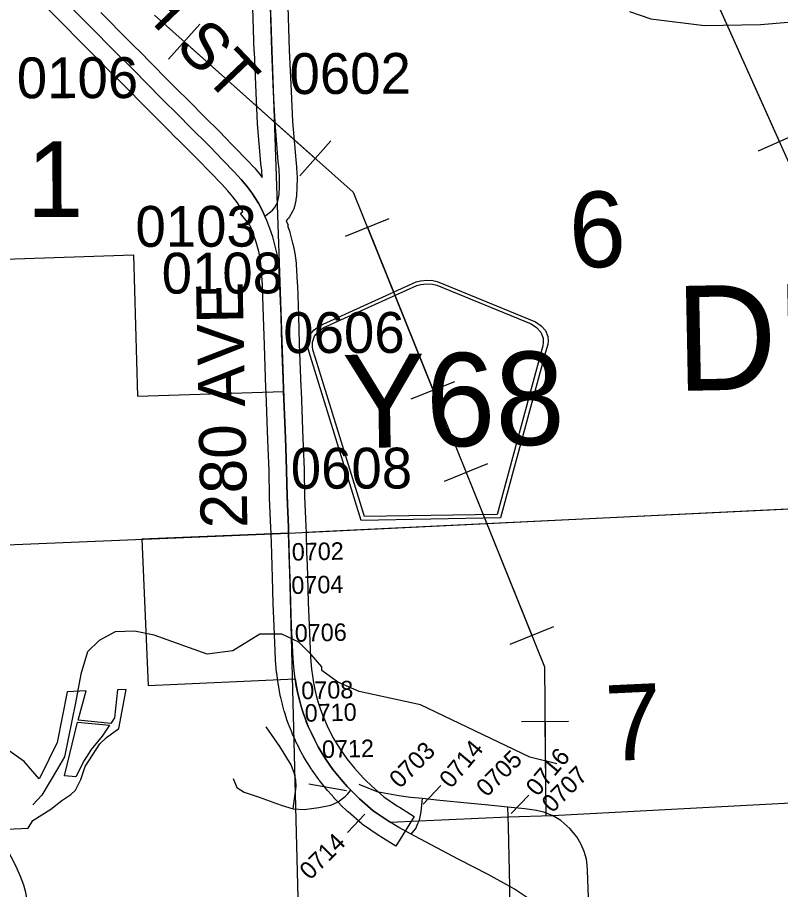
# Model space of a CAD drawing. Extents: x 128.7 to 185.5, y -21.4 to 12.6.
# Drawn here: x 151.757 to 153.067, y -8.747 to -7.251 of the extents above; entities that cross this region are included whole.
import ezdxf

# ---------------------------------------------------------------- set-up
doc = ezdxf.new("R2010")
doc.units = 0
for name, color, linetype in [('tdCoCityStreetMajor', 7, 'Continuous'), ('tdCoCityStreetMinor', 7, 'Continuous'), ('tdCoCorpBndry', 7, 'Continuous'), ('tdCoHydroRiver', 7, 'Continuous'), ('tdCoPipe', 7, 'Continuous'), ('tdCoSecRdNmbr', 7, 'Continuous'), ('tdCoSecRdTxt', 7, 'Continuous'), ('tdCoSecRteBand', 7, 'Continuous'), ('tdCoSecRteCL', 7, 'Continuous'), ('tdCoSectLine', 7, 'Continuous'), ('tdCoSectLinePart', 7, 'Continuous'), ('tdCoSectNmbr', 7, 'Continuous'), ('tdCoShieldCoRte', 7, 'Continuous'), ('tdCoSurfAsphalt', 7, 'Continuous'), ('tdCoSurfAsphaltUnbanded', 7, 'Continuous'), ('tdCoSurfBitumUnbanded', 7, 'Continuous'), ('tdCoSurfConc', 7, 'Continuous'), ('tdCoSurfConcUnbanded', 7, 'Continuous'), ('tdCoSurfGravel', 7, 'Continuous'), ('tdCoTwpNameTxt', 7, 'Continuous')]:
    doc.layers.add(name, color=color, linetype=linetype)

msp = doc.modelspace()

# ---------------------------------------------------------------- linework, layer by layer
at = {"layer": 'tdCoCityStreetMajor'}
for points in [[(152.4331, -8.6525), (152.4116, -8.6408), (152.3969, -8.6317)], [(152.4331, -8.6525), (152.4407, -8.6425), (152.4446, -8.6344), (152.4465, -8.6295)], [(152.6973, -8.8273), (152.7376, -8.7985), (152.7378, -8.7758), (152.7356, -8.7146), (152.7348, -8.7057), (152.7339, -8.6956), (152.7297, -8.6821), (152.724, -8.6692), (152.7174, -8.6572), (152.705, -8.6426), (152.6895, -8.629), (152.6754, -8.6202)], [(151.7671, -8.9262), (151.768, -8.9191), (151.7702, -8.9109), (151.7737, -8.8995), (151.7772, -8.8867), (151.7796, -8.8783), (151.779, -8.8627), (151.7774, -8.8133), (151.7764, -8.7894), (151.7758, -8.776), (151.7742, -8.7652), (151.7715, -8.7525), (151.7682, -8.7402), (151.7623, -8.7253), (151.7569, -8.712), (151.7489, -8.6955), (151.7465, -8.6911), (151.7403, -8.6792), (151.7302, -8.6651), (151.7132, -8.6461), (151.7123, -8.6452)], [(152.6973, -8.8273), (152.6944, -8.8228), (152.6742, -8.7979), (152.6584, -8.7828), (152.6409, -8.7673), (152.6103, -8.7466), (152.6022, -8.7421), (152.5652, -8.7219), (152.5146, -8.6958), (152.4392, -8.6558), (152.4331, -8.6525)]]:
    msp.add_lwpolyline(points, dxfattribs=at)
at = {"layer": 'tdCoCityStreetMinor'}
for points in [[(152.2306, -8.6088), (152.2356, -8.5706), (152.2353, -8.5597), (152.2326, -8.5491), (152.2269, -8.5333), (152.2075, -8.5018), (152.1843, -8.4682)], [(152.1274, -8.5567), (152.1337, -8.5724), (152.1466, -8.5802), (152.1724, -8.5888), (152.2099, -8.6026), (152.2306, -8.6088)], [(152.2306, -8.6088), (152.2496, -8.6103), (152.2745, -8.6068), (152.2953, -8.6024), (152.3075, -8.5972), (152.3199, -8.5876), (152.3243, -8.5831), (152.3296, -8.5772)], [(152.6034, -8.8485), (152.6029, -8.8327), (152.6025, -8.7563), (152.6022, -8.7421), (152.6002, -8.6399), (152.5996, -8.6227)]]:
    msp.add_lwpolyline(points, dxfattribs=at)
at = {"layer": 'tdCoCorpBndry'}
for points in [[(151.7011, -7.6673), (151.9564, -7.6586), (151.9636, -7.9008), (152.214, -7.8933), (152.2167, -7.9596), (152.2177, -7.9885), (152.2192, -8.0277), (152.2199, -8.0738), (152.2224, -8.1256), (152.2227, -8.1359), (151.9705, -8.1465), (151.9819, -8.3974), (152.2338, -8.3859), (152.236, -8.3993), (152.2384, -8.4109), (152.2411, -8.4222), (152.2442, -8.4333), (152.2455, -8.4374), (152.2476, -8.4444), (152.2515, -8.4553), (152.2564, -8.4675), (152.2617, -8.4794), (152.2674, -8.4912), (152.2736, -8.5027), (152.2802, -8.5141), (152.2872, -8.5251), (152.2988, -8.5414), (152.3129, -8.5586), (152.3232, -8.5705), (152.3296, -8.5772), (152.3326, -8.5803), (152.3445, -8.5917), (152.3679, -8.6122), (152.3933, -8.6294), (152.3969, -8.6317), (152.4465, -8.6295), (152.5996, -8.6227), (152.6754, -8.6202), (153.2238, -8.591)], [(151.7153, -8.645), (151.776, -8.642), (151.7836, -8.6288), (151.8147, -8.6093), (151.8334, -8.5948), (151.8487, -8.5842), (151.8571, -8.5767), (151.8659, -8.5587), (151.8738, -8.5362), (151.899, -8.4974), (151.91, -8.4868), (151.9316, -8.4714), (151.9439, -8.404), (151.9293, -8.4046), (151.9239, -8.4528), (151.9174, -8.4623), (151.8617, -8.4569), (151.875, -8.4067), (151.8429, -8.4082), (151.8256, -8.4949), (151.7967, -8.5536), (151.7947, -8.5576), (151.7688, -8.5277), (151.7376, -8.5053)]]:
    msp.add_lwpolyline(points, dxfattribs=at)
msp.add_lwpolyline([(151.8576, -8.5541), (151.838, -8.5524), (151.8605, -8.4602), (151.9152, -8.4655), (151.9025, -8.4841), (151.8841, -8.5072), (151.8718, -8.5259)], close=True, dxfattribs=at)
at = {"layer": 'tdCoHydroRiver'}
for points in [[(152.8074, -7.2411), (152.8441, -7.254), (152.9361, -7.2651), (153.0323, -7.2634), (153.1613, -7.2526)], [(152.6828, -8.5317), (152.6366, -8.5206), (152.4489, -8.4308), (152.3439, -8.4076), (152.3071, -8.3915), (152.2796, -8.3719), (152.2794, -8.3656), (152.2613, -8.3441), (152.24, -8.3228), (152.2111, -8.3095), (152.1733, -8.3093), (152.1269, -8.3377), (152.0829, -8.3439), (151.9918, -8.3108), (151.9584, -8.304), (151.9253, -8.3051), (151.8974, -8.3203), (151.8776, -8.3399), (151.8663, -8.3782), (151.8569, -8.4274), (151.838, -8.5196), (151.8261, -8.5406), (151.7992, -8.5857), (151.784, -8.602)]]:
    msp.add_lwpolyline(points, dxfattribs=at)
at = {"layer": 'tdCoPipe'}
for p, q in [((152.0168, -7.3229), (152.0704, -7.2628)), ((153.1019, -7.4479), (153.0285, -7.4808)), ((152.2417, -7.5233), (152.2953, -7.4631)), ((152.3204, -7.6265), (152.395, -7.5964)), ((152.4331, -7.9058), (152.5079, -7.8756)), ((152.49, -8.0469), (152.5646, -8.0168)), ((152.6027, -8.3262), (152.6775, -8.296)), ((152.6223, -8.4593), (152.7028, -8.4586))]:
    msp.add_line(p, q, dxfattribs=at)
for points in [[(153.2907, -13.3487), (153.1504, -13.0403), (153.08, -11.9742), (153.9221, -10.7441), (153.8422, -9.1961), (152.4885, -6.1792), (152.255, -4.5804), (152.0586, -4.5041), (150.9187, -1.6917), (149.9982, 2.3236), (149.759, 2.5022), (149.1601, 4.9961)], [(153.0651, -7.4644), (152.9418, -7.1896)], [(151.9928, -7.2474), (152.3334, -7.551), (152.6619, -8.3651), (152.6639, -8.62)], [(152.0437, -7.2928), (152.2685, -7.4932)], [(152.3578, -7.6114), (152.4705, -7.8907)], [(152.5274, -8.0318), (152.6401, -8.3111)], [(152.6626, -8.459), (152.6639, -8.62)]]:
    msp.add_lwpolyline(points, dxfattribs=at)
at = {"layer": 'tdCoSecRdNmbr'}
for p, q in [((152.2573, -8.5662), (152.3222, -8.5775)), ((152.4536, -8.6007), (152.4838, -8.5692)), ((152.6046, -8.6168), (152.6348, -8.5853)), ((152.3235, -8.6496), (152.3537, -8.6181))]:
    msp.add_line(p, q, dxfattribs=at)
at = {"layer": 'tdCoSecRteBand'}
for points in [[(152.2214, -7.2324), (152.2238, -7.3077), (152.2268, -7.378), (152.2292, -7.4296), (152.2348, -7.4956), (152.2362, -7.5074), (152.2363, -7.5085), (152.2364, -7.5097), (152.2371, -7.5259), (152.2372, -7.5269), (152.2371, -7.5278), (152.2369, -7.5419), (152.2369, -7.5424), (152.2369, -7.5429), (152.2362, -7.5566), (152.2361, -7.5584), (152.2358, -7.5601), (152.2343, -7.5687), (152.2341, -7.5697), (152.2339, -7.5706), (152.2327, -7.5758), (152.2318, -7.5795), (152.23, -7.5829), (152.2278, -7.5871), (152.2274, -7.5878), (152.227, -7.5885), (152.224, -7.5934), (152.2227, -7.5956), (152.221, -7.5976), (152.2186, -7.6004), (152.2217, -7.6075), (152.2205, -7.608), (152.2241, -7.618), (152.2245, -7.6192), (152.2248, -7.6204), (152.2295, -7.6384), (152.2296, -7.639), (152.2297, -7.6396), (152.2327, -7.6531), (152.233, -7.6544), (152.2331, -7.6556), (152.2354, -7.6727), (152.2355, -7.6737), (152.2356, -7.6747), (152.2375, -7.7065), (152.2376, -7.7069), (152.2376, -7.7073), (152.2377, -7.711), (152.2395, -7.7628), (152.2395, -7.7628), (152.2395, -7.7629), (152.241, -7.8114), (152.2437, -7.885), (152.244, -7.8921), (152.2467, -7.9584), (152.2467, -7.9585), (152.2467, -7.9586), (152.2477, -7.9874), (152.2492, -8.0266), (152.2492, -8.0269), (152.2492, -8.0272), (152.2499, -8.0729), (152.2524, -8.1242), (152.2524, -8.1245), (152.2524, -8.1248), (152.2527, -8.1351), (152.2536, -8.169), (152.2544, -8.1911), (152.2551, -8.2096), (152.2551, -8.2097), (152.2551, -8.2099), (152.2563, -8.2548), (152.2578, -8.2935), (152.2602, -8.3494), (152.2618, -8.3693), (152.2634, -8.381), (152.2653, -8.3927), (152.2677, -8.4044), (152.2702, -8.4147), (152.273, -8.4249), (152.2761, -8.4349), (152.2796, -8.4448), (152.2815, -8.4495), (152.284, -8.4558), (152.2889, -8.4668), (152.2941, -8.4775), (152.2998, -8.4881), (152.3058, -8.4984), (152.3121, -8.5083), (152.3227, -8.5232), (152.3358, -8.5393), (152.3454, -8.5503), (152.3513, -8.5565), (152.3539, -8.5592), (152.3647, -8.5696), (152.3863, -8.5884), (152.4097, -8.6043), (152.4127, -8.6062), (152.4382, -8.622), (152.4065, -8.673), (152.381, -8.6571), (152.3775, -8.6549), (152.377, -8.6546), (152.3764, -8.6543), (152.351, -8.637), (152.3495, -8.6359), (152.3481, -8.6347), (152.3247, -8.6143), (152.3242, -8.6138), (152.3237, -8.6133), (152.3119, -8.602), (152.3114, -8.6015), (152.3109, -8.601), (152.3078, -8.5978), (152.3015, -8.5911), (152.3011, -8.5907), (152.3007, -8.5902), (152.2903, -8.5784), (152.29, -8.578), (152.2896, -8.5776), (152.2756, -8.5603), (152.275, -8.5596), (152.2744, -8.5588), (152.2628, -8.5425), (152.2623, -8.5419), (152.2619, -8.5412), (152.2549, -8.5301), (152.2546, -8.5297), (152.2543, -8.5292), (152.2477, -8.5179), (152.2474, -8.5174), (152.2472, -8.5169), (152.241, -8.5054), (152.2407, -8.5049), (152.2405, -8.5044), (152.2347, -8.4926), (152.2345, -8.4921), (152.2343, -8.4916), (152.2289, -8.4796), (152.2287, -8.4791), (152.2285, -8.4786), (152.2258, -8.4718), (152.2236, -8.4665), (152.2234, -8.4659), (152.2232, -8.4653), (152.2193, -8.4543), (152.2192, -8.4538), (152.219, -8.4534), (152.2156, -8.4423), (152.2154, -8.4418), (152.2153, -8.4413), (152.2122, -8.4302), (152.2121, -8.4297), (152.2119, -8.4292), (152.2092, -8.4179), (152.2091, -8.4174), (152.209, -8.4169), (152.2064, -8.4042), (152.2063, -8.4037), (152.2062, -8.4031), (152.2042, -8.3908), (152.2042, -8.3908), (152.2042, -8.3908), (152.2041, -8.3903), (152.204, -8.3897), (152.2039, -8.3892), (152.2023, -8.3763), (152.2022, -8.3756), (152.2021, -8.3749), (152.2004, -8.3537), (152.2003, -8.3531), (152.2003, -8.3526), (152.1978, -8.2961), (152.1978, -8.296), (152.1978, -8.2959), (152.1964, -8.2569), (152.1963, -8.2568), (152.1963, -8.2566), (152.1951, -8.2116), (152.1944, -8.1933), (152.1936, -8.1711), (152.1936, -8.171), (152.1936, -8.1708), (152.1927, -8.1368), (152.1924, -8.1267), (152.19, -8.0752), (152.1899, -8.0748), (152.1899, -8.0743), (152.1892, -8.0285), (152.1877, -7.9896), (152.1877, -7.9896), (152.1877, -7.9895), (152.1867, -7.9608), (152.1841, -7.8945), (152.1838, -7.8874), (152.1838, -7.8873), (152.1838, -7.8872), (152.1811, -7.8135), (152.1811, -7.8134), (152.1811, -7.8133), (152.1796, -7.7648), (152.1777, -7.7131), (152.1776, -7.7098), (152.1757, -7.6794), (152.1738, -7.6647), (152.1713, -7.6529), (152.167, -7.6367), (152.1624, -7.6235), (152.1577, -7.611), (152.1563, -7.6079), (152.14, -7.5874), (152.1441, -7.5841), (152.1348, -7.5695), (152.1272, -7.5593), (152.1185, -7.5486), (152.1077, -7.5367), (152.0885, -7.5175), (152.0882, -7.5172), (152.088, -7.517), (152.0658, -7.4939), (152.0313, -7.4596), (152.0312, -7.4595), (152.0311, -7.4594), (152.0139, -7.4419), (151.9829, -7.4109), (151.9829, -7.4109), (151.9828, -7.4108), (151.9346, -7.3621), (151.9063, -7.3341), (151.9062, -7.334), (151.9061, -7.3339), (151.8578, -7.2851), (151.8578, -7.285), (151.8577, -7.285), (151.8413, -7.2684), (151.7973, -7.2246)], [(152.1771, -7.5258), (152.1765, -7.5135), (152.1751, -7.5023), (152.1751, -7.5017), (152.175, -7.5012), (152.1694, -7.4341), (152.1693, -7.4336), (152.1693, -7.433), (152.1668, -7.3807), (152.1668, -7.3807), (152.1668, -7.3806), (152.1639, -7.3101), (152.1639, -7.3099), (152.1638, -7.3098), (152.1614, -7.2344)], [(151.9005, -7.2429), (151.9487, -7.2916), (151.9769, -7.3196), (151.977, -7.3197), (151.9771, -7.3198), (152.0254, -7.3686), (152.0564, -7.3996), (152.0565, -7.3997), (152.0566, -7.3997), (152.0737, -7.4171), (152.1084, -7.4515), (152.1086, -7.4518), (152.1089, -7.4521), (152.1311, -7.4753), (152.1506, -7.4948), (152.1512, -7.4953), (152.1517, -7.4959), (152.1635, -7.5089), (152.164, -7.5095), (152.1645, -7.5101), (152.1742, -7.522), (152.1746, -7.5225), (152.1749, -7.523), (152.1771, -7.5258)]]:
    msp.add_lwpolyline(points, dxfattribs=at)
at = {"layer": 'tdCoSecRteCL'}
msp.add_line((152.5996, -8.6227), (152.599, -8.6055), dxfattribs=at)
for points in [[(151.7369, -7.1161), (151.7755, -7.1594), (151.8184, -7.2033), (151.8626, -7.2472), (151.8791, -7.264), (151.9274, -7.3128), (151.9558, -7.3409), (152.0041, -7.3897), (152.0352, -7.4208), (152.0525, -7.4383), (152.0872, -7.4728), (152.1097, -7.4963), (152.1294, -7.516), (152.1413, -7.5291), (152.1509, -7.5409), (152.1595, -7.5525), (152.1708, -7.5702), (152.1775, -7.5818), (152.1821, -7.5922)], [(152.1821, -7.5922), (152.1914, -7.5849), (152.1951, -7.5817), (152.1983, -7.578), (152.2013, -7.573), (152.2035, -7.5688), (152.2047, -7.5637), (152.2062, -7.555), (152.2069, -7.5413), (152.2072, -7.5273), (152.2064, -7.511), (152.2049, -7.4987), (152.1993, -7.4316), (152.1968, -7.3793), (152.1938, -7.3088), (152.1914, -7.2333)], [(152.3969, -8.6317), (152.3933, -8.6294), (152.3679, -8.6122), (152.3445, -8.5917), (152.3326, -8.5803), (152.3296, -8.5772), (152.3232, -8.5705), (152.3129, -8.5586), (152.2988, -8.5414), (152.2872, -8.5251), (152.2802, -8.5141), (152.2736, -8.5027), (152.2674, -8.4912), (152.2617, -8.4794), (152.2564, -8.4675), (152.2536, -8.4607), (152.2515, -8.4553), (152.2476, -8.4444), (152.2442, -8.4333), (152.2411, -8.4222), (152.2384, -8.4109), (152.2358, -8.3982), (152.2338, -8.3859), (152.2337, -8.3854), (152.232, -8.3725), (152.2303, -8.3512), (152.2278, -8.2948), (152.2263, -8.2558), (152.2251, -8.2107), (152.2244, -8.1922), (152.2236, -8.17), (152.2227, -8.1359), (152.2224, -8.1256), (152.2199, -8.0738), (152.2192, -8.0277), (152.2177, -7.9885), (152.2167, -7.9596), (152.214, -7.8933), (152.2138, -7.8861), (152.211, -7.8124), (152.2096, -7.7638), (152.2077, -7.7121), (152.2076, -7.7083), (152.2056, -7.6765), (152.2034, -7.6595), (152.2004, -7.646), (152.1958, -7.6279), (152.1906, -7.6132), (152.1854, -7.5996), (152.1821, -7.5922)], [(152.3433, -8.5664), (152.3741, -8.579), (152.4118, -8.5861), (152.4318, -8.5888), (152.4524, -8.5909)], [(152.4465, -8.6295), (152.4481, -8.6253), (152.45, -8.6142), (152.4524, -8.5909)], [(152.4524, -8.5909), (152.4762, -8.5933), (152.5354, -8.599), (152.56, -8.6014), (152.599, -8.6055)], [(152.599, -8.6055), (152.6281, -8.6086), (152.6481, -8.6113), (152.6599, -8.6142), (152.6754, -8.6202)]]:
    msp.add_lwpolyline(points, dxfattribs=at)
at = {"layer": 'tdCoSectLine'}
for points in [[(152.1881, -7.1424), (152.2223, -8.1359)], [(152.2223, -8.1359), (153.2084, -8.088)], [(151.2135, -8.178), (152.2223, -8.1359)], [(152.2223, -8.1359), (152.2482, -9.1419)]]:
    msp.add_lwpolyline(points, dxfattribs=at)
at = {"layer": 'tdCoSectLinePart'}
msp.add_lwpolyline([(152.2518, -8.1345), (153.1785, -8.0895)], dxfattribs=at)
at = {"layer": 'tdCoShieldCoRte'}
for points in [[(152.347, -8.1142), (152.2602, -7.8328), (152.2561, -7.8197), (152.2552, -7.8138), (152.2551, -7.806), (152.2592, -7.7956), (152.2663, -7.787), (152.2757, -7.7801), (152.4417, -7.7049), (152.4492, -7.7031), (152.4596, -7.702), (152.4701, -7.7028), (152.4776, -7.7043), (152.6461, -7.7737), (152.6558, -7.7802), (152.6632, -7.7885), (152.6677, -7.7988), (152.6678, -7.8066), (152.6672, -7.8125), (152.6635, -7.8257), (152.5865, -8.11)], [(152.3528, -8.1077), (152.2683, -7.8339), (152.2643, -7.8213), (152.2635, -7.8157), (152.2634, -7.8082), (152.2673, -7.7982), (152.2741, -7.79), (152.2832, -7.7834), (152.4426, -7.7112), (152.4497, -7.7095), (152.4597, -7.7084), (152.4698, -7.7091), (152.477, -7.7106), (152.6388, -7.7772), (152.6481, -7.7834), (152.6552, -7.7915), (152.6594, -7.8013), (152.6596, -7.8088), (152.659, -7.8145), (152.6555, -7.8272), (152.5806, -8.1038)]]:
    msp.add_lwpolyline(points, close=True, dxfattribs=at)
at = {"layer": 'tdCoSurfAsphalt'}
msp.add_lwpolyline([(152.3969, -8.6317), (152.3933, -8.6294), (152.3679, -8.6122), (152.3445, -8.5917), (152.3326, -8.5803), (152.3296, -8.5772), (152.3232, -8.5705), (152.3129, -8.5586), (152.2988, -8.5414), (152.2872, -8.5251), (152.2802, -8.5141), (152.2736, -8.5027), (152.2674, -8.4912), (152.2617, -8.4794), (152.2564, -8.4675), (152.2536, -8.4607), (152.2515, -8.4553), (152.2476, -8.4444), (152.2442, -8.4333), (152.2411, -8.4222), (152.2384, -8.4109), (152.2358, -8.3982), (152.2338, -8.3859), (152.2337, -8.3854), (152.232, -8.3725), (152.2303, -8.3512), (152.2278, -8.2948), (152.2263, -8.2558), (152.2251, -8.2107), (152.2244, -8.1922)], dxfattribs=at)
at = {"layer": 'tdCoSurfAsphaltUnbanded'}
msp.add_line((152.5996, -8.6227), (152.599, -8.6055), dxfattribs=at)
at = {"layer": 'tdCoSurfBitumUnbanded'}
msp.add_lwpolyline([(152.4465, -8.6295), (152.4481, -8.6253), (152.45, -8.6142), (152.4524, -8.5909)], dxfattribs=at)
at = {"layer": 'tdCoSurfConc'}
msp.add_lwpolyline([(152.2244, -8.1922), (152.2236, -8.17), (152.2227, -8.1359), (152.2224, -8.1256), (152.2199, -8.0738), (152.2192, -8.0277), (152.2177, -7.9885), (152.2167, -7.9596), (152.214, -7.8933), (152.2138, -7.8861), (152.211, -7.8124), (152.2096, -7.7638), (152.2077, -7.7121), (152.2076, -7.7083), (152.2056, -7.6765), (152.2034, -7.6595), (152.2004, -7.646), (152.1958, -7.6279), (152.1906, -7.6132), (152.1854, -7.5996), (152.1821, -7.5922), (152.1775, -7.5818), (152.1708, -7.5702), (152.1595, -7.5525), (152.1509, -7.5409), (152.1413, -7.5291), (152.1294, -7.516), (152.1097, -7.4963), (152.0872, -7.4728), (152.0525, -7.4383), (152.0352, -7.4208), (152.0041, -7.3897), (151.9558, -7.3409), (151.9274, -7.3128), (151.8791, -7.264), (151.8626, -7.2472)], dxfattribs=at)
at = {"layer": 'tdCoSurfConcUnbanded'}
msp.add_lwpolyline([(152.3433, -8.5664), (152.3741, -8.579), (152.4118, -8.5861), (152.4318, -8.5888), (152.4524, -8.5909), (152.4762, -8.5933), (152.5354, -8.599), (152.56, -8.6014), (152.599, -8.6055), (152.6281, -8.6086), (152.6481, -8.6113), (152.6599, -8.6142), (152.6754, -8.6202)], dxfattribs=at)
at = {"layer": 'tdCoSurfGravel'}
msp.add_lwpolyline([(152.1821, -7.5922), (152.1914, -7.5849), (152.1951, -7.5817), (152.1983, -7.578), (152.2013, -7.573), (152.2035, -7.5688), (152.2047, -7.5637), (152.2062, -7.555), (152.2069, -7.5413), (152.2072, -7.5273), (152.2064, -7.511), (152.2049, -7.4987), (152.1993, -7.4316), (152.1968, -7.3793), (152.1938, -7.3088), (152.1914, -7.2333)], dxfattribs=at)

# ---------------------------------------------------------------- texts
at = {"layer": 'tdCoSecRdNmbr'}
for s, height, rotation, p in [('0602', 0.07, 0.1154, (152.2243, -7.3827)), ('0106', 0.07, 0.1149, (151.7563, -7.39)), ('0103', 0.07, 0.1149, (151.9599, -7.6449)), ('0108', 0.07, 0.1149, (152.0049, -7.7251)), ('0606', 0.07, 0.1154, (152.2136, -7.8271)), ('0608', 0.07, 0.1154, (152.2264, -8.0598)), ('0702', 0.03, 1.1824, (152.2284, -8.1833)), ('0704', 0.03, 1.1824, (152.2277, -8.2404)), ('0706', 0.03, 1.1824, (152.2335, -8.3225)), ('0708', 0.03, 1.1824, (152.2447, -8.421)), ('0710', 0.03, 1.1824, (152.2505, -8.4596)), ('0712', 0.03, 1.1824, (152.2802, -8.5218)), ('0703', 0.03, 45.1143, (152.4135, -8.5754)), ('0714', 0.03, 50.1154, (152.5015, -8.5755)), ('0705', 0.03, 45.1143, (152.5627, -8.5901)), ('0716', 0.03, 50.1154, (152.65, -8.5891)), ('0707', 0.03, 45.1143, (152.6751, -8.6173)), ('0714', 0.03, 45.1143, (152.2595, -8.7324))]:
    msp.add_text(s, height=height, rotation=rotation, dxfattribs=at).set_placement(p)
at = {"layer": 'tdCoSecRdTxt'}
for s, rotation, p in [('218TH ST', 313.6622, (151.7838, -7.0481)), ('280 AVE', 91.1117, (152.152, -8.1269))]:
    msp.add_text(s, height=0.08, rotation=rotation, dxfattribs=at).set_placement(p)
at = {"layer": 'tdCoSectNmbr'}
for s, rotation, p in [('1', 0.115, (151.7739, -7.5938)), ('6', 2.6681, (152.7068, -7.6822)), ('7', 2.6681, (152.7694, -8.5274))]:
    msp.add_text(s, height=0.13, rotation=rotation, dxfattribs=at).set_placement(p)
at = {"layer": 'tdCoShieldCoRte'}
msp.add_text('Y68', height=0.16, rotation=1, dxfattribs=at).set_placement((152.3167, -7.9904))
at = {"layer": 'tdCoTwpNameTxt'}
msp.add_text('DE WITT', height=0.18, rotation=1.1165, dxfattribs=at).set_placement((152.8882, -7.8922))

doc.saveas('drawing.dxf')
